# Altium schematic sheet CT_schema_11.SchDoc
size 274 x 160 mm
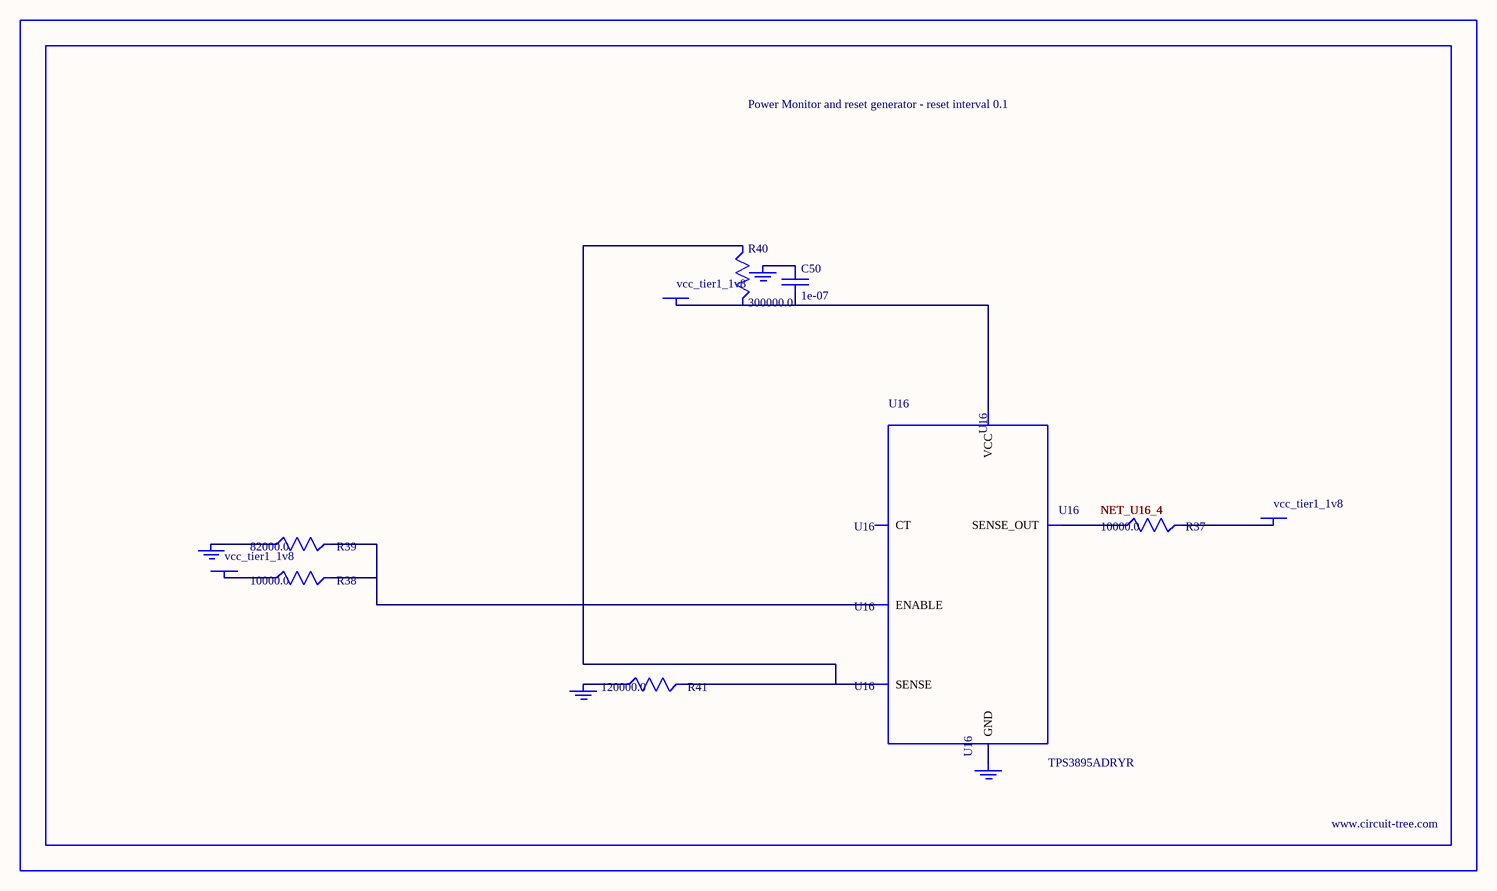
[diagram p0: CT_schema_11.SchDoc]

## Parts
BORDER10  (no value)
C50  1e-07  [C0402]
GND_INSTANCE_10_0  (no value)
GND_INSTANCE_10_1  (no value)
GND_INSTANCE_10_2  (no value)
GND_INSTANCE_10_3  (no value)
POWER_INSTANCE_10_0  vcc_tier1_1v8
POWER_INSTANCE_10_1  vcc_tier1_1v8
POWER_INSTANCE_10_2  vcc_tier1_1v8
R37  10000.0  [R0603]
R38  10000.0  [R0603]
R39  82000.0  [R0603]
R40  300000.0  [R0603]
R41  120000.0  [R0603]
U16  TPS3895ADRYR  [SON-6]

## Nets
NetC50_1: C50.1 GND_INSTANCE_10_2.0(GND)
NetC50_2: C50.2 POWER_INSTANCE_10_2.0(PWR) R40.2 U16.6(VCC)
NetGND_INSTANCE_10_0_0: GND_INSTANCE_10_0.0(GND) R39.1
NetGND_INSTANCE_10_1_0: GND_INSTANCE_10_1.0(GND) R41.1
NetGND_INSTANCE_10_3_0: GND_INSTANCE_10_3.0(GND) U16.2(GND)
NetPOWER_INSTANCE_10_0_0: POWER_INSTANCE_10_0.0(PWR) R38.1
NetPOWER_INSTANCE_10_1_0: POWER_INSTANCE_10_1.0(PWR) R37.2
NetR37_1: R37.1 U16.4(SENSE_OUT)
NetR38_2: R38.2 R39.2 U16.1(ENABLE)
NetR40_1: R40.1 R41.2 U16.3(SENSE)

Not connected (* = marked no-connect by the designer): U16 5(CT)

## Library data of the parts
BORDER10 = BORDER_PAGE10
C50 = C0402C104K3RACTU
GND_INSTANCE_10_0-GND_INSTANCE_10_3 = GND
POWER_INSTANCE_10_0-POWER_INSTANCE_10_2 = PWR
R37 R38 = RC0603JR-0710KL
R39 = RC0603JR-0782KL
R40 = RC0603JR-07300KL
R41 = RC0603JR-07120KL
